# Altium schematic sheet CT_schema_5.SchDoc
size 260 x 245 mm
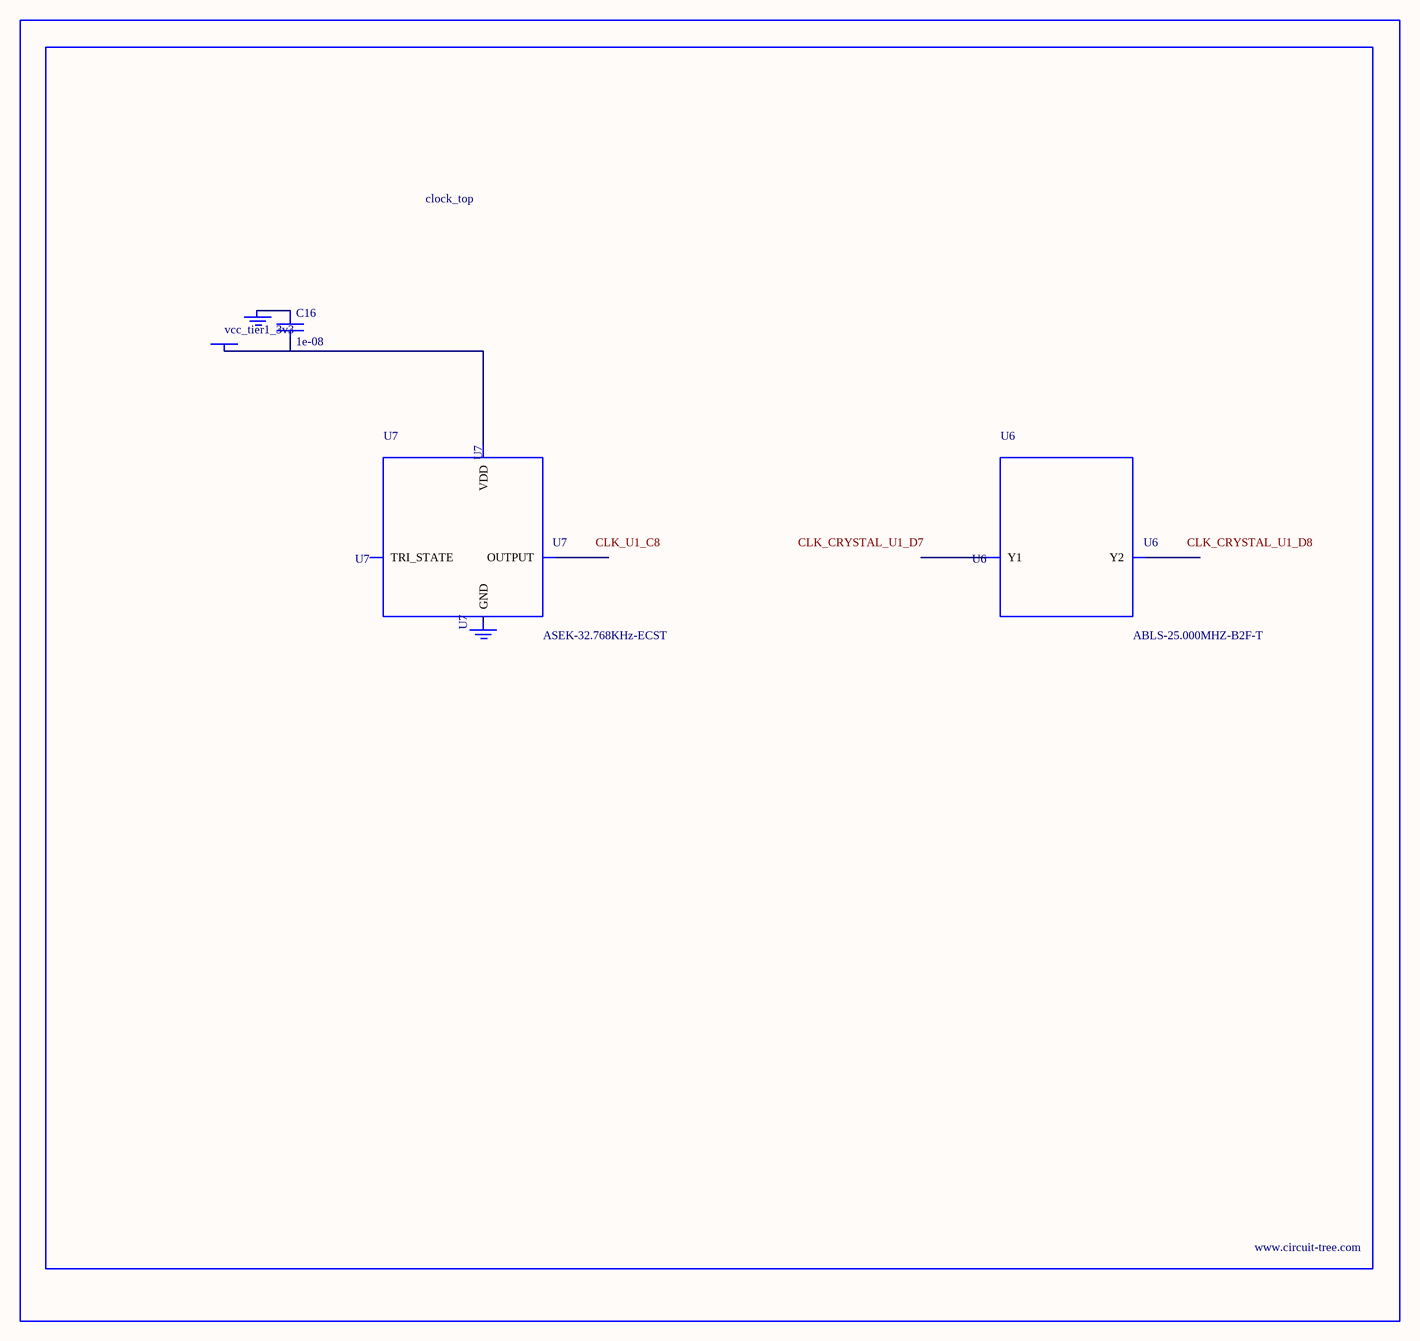
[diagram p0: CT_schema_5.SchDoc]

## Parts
BORDER4  (no value)
C16  1e-08  [C0402]
GND_INSTANCE_4_0  (no value)
GND_INSTANCE_4_1  (no value)
POWER_INSTANCE_4_0  vcc_tier1_3v3
U6  ABLS-25.000MHZ-B2F-T  [ABLS-25.000MHZ-B2F-T]
U7  ASEK-32.768KHz-ECST  [ASEK]

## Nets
NetC16_1: C16.1 GND_INSTANCE_4_0.0(GND)
NetC16_2: C16.2 POWER_INSTANCE_4_0.0(PWR) U7.4(VDD)

Not connected (* = marked no-connect by the designer): GND_INSTANCE_4_1 0(GND); U6 1(Y1) 2(Y2); U7 1(TRI_STATE) 2(GND) 3(OUTPUT)

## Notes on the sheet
- Labels drawn without touching a wire or pin: CLK_CRYSTAL_U1_D7, CLK_CRYSTAL_U1_D8, CLK_U1_C8

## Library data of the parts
BORDER4 = BORDER_PAGE4
C16 = C0402C103K3RAC
GND_INSTANCE_4_0 GND_INSTANCE_4_1 = GND
POWER_INSTANCE_4_0 = PWR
